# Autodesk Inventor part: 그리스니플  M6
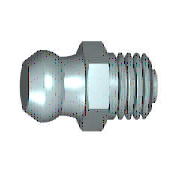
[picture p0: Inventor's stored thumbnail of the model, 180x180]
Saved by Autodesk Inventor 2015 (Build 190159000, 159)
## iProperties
IsCustomPart: 1
Created: 2012-02
Part Number: 그리스니플  M6
Material: 강철, 연강
Description: 그리스 니플에 대한 사양. 제I부: 버튼 머리 그리스 니플 유형 A
Document SubType Name: Modeling
Standard: IS 4009
Designer: mduedu
Standards Organization: IS
Language: ko-KR
Size Designation: M6 원추 짧은
Categories: <MemberInstance><Categories><Category DisplayName="기타 부품" InternalName="5aa15e00-363f-49f2-933f-16f664388e3f" Mnemonic="OTHER"><Category DisplayName="그리스 부속품" I
Density: 1 g/cm^3
Appearance: 강철
Author: mduedu
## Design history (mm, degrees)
sketch "스케치1"
  geometry: L1 (-9.8, 0)-(-9.8, 2.25); L2 (-9.8, 2.25)-(-8.055, 3.194); L3 (-9.8, 0)-(6.2, 0); L4 (6.2, 0)-(6.2, 1.5); L5 (6.2, 1.5)-(5.5, 1.5); L6 (5.5, 1.5)-(5.5, 3); L7 (5.5, 3)-(0, 3); L8 (-13, 0)-(9.4, 0) reference; L9 (0, -1.725)-(0, 10.35) reference; L10 (-3, 3.5)-(0, 3.5); L11 (0, 3.5)-(0, 3); A1 r 3.25 centre (-7.455, 0) between (-5.573, 2.65) and (-8.055, 3.194); A2 r 6 centre (-6.12, 8.625) between (-5.573, 2.65) and (-3, 3.5)
  constraints: 18 end point, 5 perpendicular, 4 point on circle, 2 centre point, 2 parallel, 2 point on line, 1 collinear, 1 vertical
  dimensions: "d0" = 16 distance between parallel lines of L1 L4 (= GL); "d1" = 5.3 diameter of A1.start L3 (= KGB2); "d2" = 0.7 distance between parallel lines of L4 L6 (= PHH); "d3" = 3 diameter of L5 L3 (= 0.5 x NND); "d4" = 6 diameter of L7 L3 (= NND); "d5" = 6.5 dimension on A1 L3 (= KR); "d6" = 4.5 diameter of L1.end L3 (= KGB1); "d7" = 6 radius of A2 (= RBN); "d11" = 7 diameter of L10.start L3 (= SW); "d14" = 3 distance of L10.start L10.end (= KOH); "d15" = 5.5 distance between parallel lines of L6 L11 (= NLG); "d61" = 8.05479 distance from line of L9 L2.end (computed from KGB1, KR, PHH, GL, NLG, VERS); "d62" = 7.45479 distance from line of L9 A1.centre (computed from NLG, GL, PHH, KR, KGB1)
revolve "본체" sketch "스케치1" stored, may be unused: angle "d25" = 90 deg
sketch "스케치2"
  geometry: L1 (2.021, 3.5)-(4.041, 0); L2 (4.041, 0)-(2.021, -3.5); L3 (2.021, -3.5)-(-2.021, -3.5); L4 (-2.021, -3.5)-(-4.041, 0); L5 (-4.041, 0)-(-2.021, 3.5); L6 (-2.021, 3.5)-(2.021, 3.5); C1 r 3.5 at (0, 0) reference; 1 further point
  constraints: 12 end point, 1 coincident, 1 horizontal, 1 tangent, 11 other
extrude "머리" join sketch "스케치2" distance "d17" = 3 (= KOH); taper "d18" = 0 deg
sketch "스케치3"
  geometry: L1 (2.687, 4.041)-(3, 4.041); L2 (3, 4.041)-(3, 3.5); L3 (3, 3.5)-(2.687, 4.041); L4 (0.313, 4.041)-(0, 4.041); L5 (0, 4.041)-(0, 3.5); L6 (0, 3.5)-(0.313, 4.041); L7 (3.6, 0)-(-0.6, 0) reference; L8 (0, 4.041)-(0, 2.021) reference; L9 (0, 4.041)-(3, 4.041) reference; L10 (3, 3.031)-(3, 4.041) reference
  constraints: 12 end point, 4 collinear, 3 perpendicular, 1 horizontal
  dimensions: "d19" = 3.5 distance from line of L5.end L7 (= 0.5 x SW); "d20" = 3.5 distance from line of L2.end L7 (= 0.5 x SW); "d21" = 30 deg angle of L6 L5; "d22" = 30 deg angle of L2 L3
revolve "모따기1" sketch "스케치3" stored, may be unused: angle "d56" = 90 deg
body "Solid1"
fillet "모깎기1" dims "d8" = 0.2 (= RR)
feature "스레드1" dims "d9" = 4.88655 (= NLG - GAL), "d10" = 0
chamfer "모따기2" distance "d23" = 0.61345 (= -0.5 x GD1 + 0.5 x NND); stored, may be unused: angle "d24" = 45 deg, second distance "d59" = 0.61345 (= -0.5 x GD1 + 0.5 x NND)
other parameters: "NLG" = 5.5 [user parameter; used in 4 equation terms], "GL" = 16 [user parameter; used in 3 equation terms], "NND" = 6 [user parameter; used in 4 equation terms], "KGB1" = 4.5 [user parameter; used in 3 equation terms], "KGB2" = 5.3 [user parameter; used in 1 equation term], "VERS" = 0.6 [user parameter; used in 1 equation term], "KR" = 6.5 [user parameter; used in 3 equation terms], "RBN" = 6 [user parameter; used in 1 equation term], "SW" = 7 [user parameter; used in 3 equation terms], "KOH" = 3 [user parameter; used in 2 equation terms], "GAL" = 0.61345 (= 0.61345 x PTC) [user parameter; used in 1 equation term], "FAWI" = 45 deg [user parameter], "PHH" = 0.7 [user parameter; used in 3 equation terms], "GD1" = 4.7731 (= THREADDIA - 1.2269 x PTC) [user parameter; used in 2 equation terms], "RR" = 0.2 [user parameter; used in 1 equation term], "d12" = 0, "d13" = 0, "GUL" = 0.61345 (= 0.61345 x PTC) [user parameter], "DULO" = 1.5 [user parameter], "PTC" = 1 [user parameter; used in 4 equation terms], "GEL" = 5.5 [user parameter], "THREADDIA" = 6 [user parameter; used in 1 equation term], "TOA" = 30 deg [user parameter]
